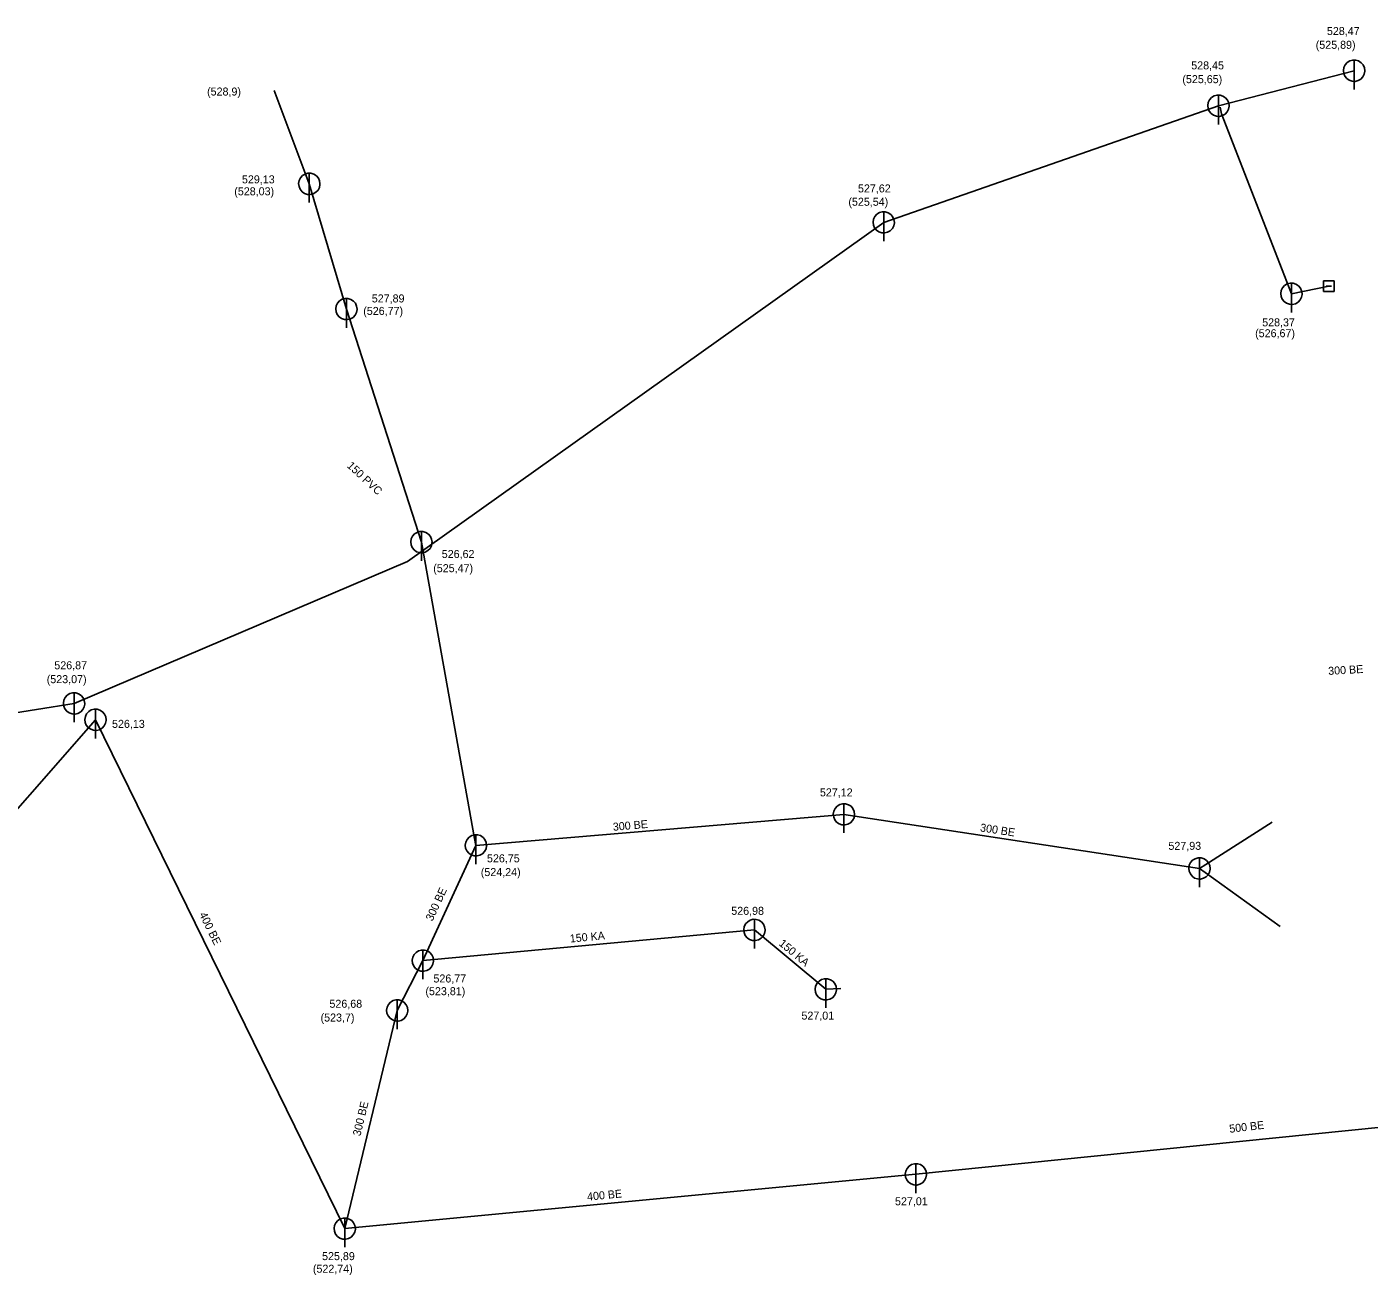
# Model space of a CAD drawing. Extents: x -476058 to -471893, y -1155786 to -1152000.
# Drawn here: x -473628.2 to -473502.4, y -1153925.1 to -1153808.2 of the extents above; entities that cross this region are included whole.
import ezdxf

# ---------------------------------------------------------------- set-up
doc = ezdxf.new("R2010")
doc.units = 0
for name, color, linetype in [('Vrstva 10', 7, 'Continuous'), ('Vrstva 18', 7, 'Continuous'), ('Vrstva 19', 7, 'Continuous'), ('Vrstva 3', 7, 'Continuous'), ('Vrstva 35', 7, 'Continuous'), ('Vrstva 4', 7, 'Continuous'), ('Vrstva 45', 7, 'Continuous'), ('Vrstva 46', 7, 'Continuous'), ('Vrstva 50', 7, 'Continuous'), ('Vrstva 51', 7, 'Continuous')]:
    doc.layers.add(name, color=color, linetype=linetype)

msp = doc.modelspace()

# ---------------------------------------------------------------- linework, layer by layer
at = {"layer": 'Vrstva 10'}
for p, q in [((-473503.76, -1153811.26), (-473503.76, -1153814.01)), ((-473516.48, -1153814.54), (-473516.48, -1153817.29)), ((-473601.71, -1153821.86), (-473601.71, -1153824.61)), ((-473547.86, -1153825.48), (-473547.86, -1153828.23)), ((-473509.64, -1153832.17), (-473509.64, -1153834.92)), ((-473505.64, -1153831.96), (-473506.64, -1153831.96)), ((-473506.64, -1153831.96), (-473506.64, -1153832.96)), ((-473505.64, -1153832.96), (-473505.64, -1153831.96)), ((-473598.23, -1153833.6), (-473598.23, -1153836.35)), ((-473506.64, -1153832.96), (-473505.64, -1153832.96)), ((-473505.89, -1153832.46), (-473506.39, -1153832.46)), ((-473591.2, -1153855.45), (-473591.2, -1153858.19)), ((-473623.76, -1153870.56), (-473623.76, -1153873.31)), ((-473621.75, -1153872.09), (-473621.75, -1153874.84)), ((-473551.59, -1153880.96), (-473551.59, -1153883.7)), ((-473586.08, -1153883.86), (-473586.08, -1153886.61)), ((-473518.26, -1153886.02), (-473518.26, -1153888.77)), ((-473559.98, -1153891.79), (-473559.98, -1153894.53)), ((-473591.06, -1153894.66), (-473591.06, -1153897.41)), ((-473553.29, -1153897.35), (-473553.29, -1153900.1)), ((-473593.46, -1153899.33), (-473593.46, -1153902.08)), ((-473544.84, -1153914.69), (-473544.84, -1153917.44)), ((-473598.39, -1153919.78), (-473598.39, -1153922.53))]:
    msp.add_line(p, q, dxfattribs=at)
for points in [[(-473502.76, -1153812.26), (-473502.8, -1153811.98), (-473502.92, -1153811.72), (-473503.1, -1153811.51), (-473503.34, -1153811.35), (-473503.6, -1153811.27), (-473503.89, -1153811.27), (-473504.16, -1153811.34), (-473504.4, -1153811.49), (-473504.59, -1153811.7), (-473504.71, -1153811.95), (-473504.76, -1153812.23), (-473504.73, -1153812.51), (-473504.62, -1153812.77), (-473504.44, -1153812.99), (-473504.21, -1153813.15), (-473503.94, -1153813.24), (-473503.66, -1153813.26), (-473503.39, -1153813.19), (-473503.14, -1153813.05), (-473502.95, -1153812.84), (-473502.82, -1153812.59), (-473502.76, -1153812.32), (-473502.76, -1153812.26)], [(-473515.48, -1153815.54), (-473515.52, -1153815.27), (-473515.64, -1153815.01), (-473515.82, -1153814.79), (-473516.06, -1153814.64), (-473516.33, -1153814.56), (-473516.61, -1153814.55), (-473516.88, -1153814.63), (-473517.12, -1153814.78), (-473517.31, -1153814.99), (-473517.43, -1153815.24), (-473517.48, -1153815.52), (-473517.45, -1153815.8), (-473517.34, -1153816.06), (-473517.16, -1153816.28), (-473516.93, -1153816.44), (-473516.67, -1153816.53), (-473516.38, -1153816.54), (-473516.11, -1153816.47), (-473515.86, -1153816.33), (-473515.67, -1153816.13), (-473515.54, -1153815.88), (-473515.48, -1153815.6), (-473515.48, -1153815.54)], [(-473600.71, -1153822.86), (-473600.74, -1153822.58), (-473600.86, -1153822.33), (-473601.04, -1153822.11), (-473601.28, -1153821.96), (-473601.55, -1153821.88), (-473601.83, -1153821.87), (-473602.1, -1153821.95), (-473602.35, -1153822.09), (-473602.54, -1153822.3), (-473602.66, -1153822.56), (-473602.71, -1153822.84), (-473602.67, -1153823.12), (-473602.57, -1153823.38), (-473602.39, -1153823.6), (-473602.16, -1153823.76), (-473601.89, -1153823.85), (-473601.61, -1153823.86), (-473601.33, -1153823.79), (-473601.09, -1153823.65), (-473600.89, -1153823.45), (-473600.76, -1153823.2), (-473600.71, -1153822.92), (-473600.71, -1153822.86)], [(-473546.86, -1153826.48), (-473546.9, -1153826.2), (-473547.02, -1153825.94), (-473547.2, -1153825.73), (-473547.44, -1153825.57), (-473547.71, -1153825.49), (-473547.99, -1153825.49), (-473548.26, -1153825.56), (-473548.5, -1153825.71), (-473548.69, -1153825.92), (-473548.81, -1153826.17), (-473548.86, -1153826.45), (-473548.83, -1153826.73), (-473548.72, -1153826.99), (-473548.54, -1153827.21), (-473548.31, -1153827.37), (-473548.04, -1153827.46), (-473547.76, -1153827.47), (-473547.49, -1153827.41), (-473547.24, -1153827.27), (-473547.05, -1153827.06), (-473546.92, -1153826.81), (-473546.86, -1153826.53), (-473546.86, -1153826.48)], [(-473508.64, -1153833.17), (-473508.68, -1153832.89), (-473508.8, -1153832.63), (-473508.98, -1153832.42), (-473509.22, -1153832.27), (-473509.48, -1153832.18), (-473509.77, -1153832.18), (-473510.04, -1153832.25), (-473510.28, -1153832.4), (-473510.47, -1153832.61), (-473510.59, -1153832.86), (-473510.64, -1153833.14), (-473510.61, -1153833.42), (-473510.5, -1153833.68), (-473510.32, -1153833.9), (-473510.09, -1153834.06), (-473509.82, -1153834.15), (-473509.54, -1153834.17), (-473509.27, -1153834.1), (-473509.02, -1153833.96), (-473508.83, -1153833.75), (-473508.7, -1153833.5), (-473508.64, -1153833.23), (-473508.64, -1153833.17)], [(-473597.23, -1153834.6), (-473597.27, -1153834.32), (-473597.39, -1153834.06), (-473597.57, -1153833.85), (-473597.81, -1153833.69), (-473598.08, -1153833.61), (-473598.36, -1153833.61), (-473598.63, -1153833.68), (-473598.87, -1153833.83), (-473599.06, -1153834.04), (-473599.18, -1153834.29), (-473599.23, -1153834.57), (-473599.2, -1153834.85), (-473599.09, -1153835.11), (-473598.91, -1153835.33), (-473598.68, -1153835.49), (-473598.41, -1153835.58), (-473598.13, -1153835.59), (-473597.86, -1153835.53), (-473597.61, -1153835.39), (-473597.42, -1153835.18), (-473597.29, -1153834.93), (-473597.23, -1153834.65), (-473597.23, -1153834.6)], [(-473590.2, -1153856.45), (-473590.24, -1153856.17), (-473590.36, -1153855.91), (-473590.54, -1153855.7), (-473590.78, -1153855.54), (-473591.05, -1153855.46), (-473591.33, -1153855.45), (-473591.6, -1153855.53), (-473591.84, -1153855.68), (-473592.03, -1153855.89), (-473592.16, -1153856.14), (-473592.2, -1153856.42), (-473592.17, -1153856.7), (-473592.06, -1153856.96), (-473591.89, -1153857.18), (-473591.65, -1153857.34), (-473591.39, -1153857.43), (-473591.1, -1153857.44), (-473590.83, -1153857.37), (-473590.59, -1153857.23), (-473590.39, -1153857.03), (-473590.26, -1153856.78), (-473590.21, -1153856.5), (-473590.2, -1153856.45)], [(-473622.76, -1153871.56), (-473622.8, -1153871.28), (-473622.92, -1153871.02), (-473623.1, -1153870.81), (-473623.34, -1153870.66), (-473623.6, -1153870.57), (-473623.89, -1153870.57), (-473624.16, -1153870.64), (-473624.4, -1153870.79), (-473624.59, -1153871), (-473624.71, -1153871.25), (-473624.76, -1153871.53), (-473624.73, -1153871.81), (-473624.62, -1153872.07), (-473624.44, -1153872.29), (-473624.21, -1153872.45), (-473623.94, -1153872.54), (-473623.66, -1153872.56), (-473623.39, -1153872.49), (-473623.14, -1153872.35), (-473622.95, -1153872.14), (-473622.82, -1153871.89), (-473622.76, -1153871.62), (-473622.76, -1153871.56)], [(-473620.75, -1153873.09), (-473620.79, -1153872.81), (-473620.91, -1153872.55), (-473621.09, -1153872.34), (-473621.33, -1153872.19), (-473621.6, -1153872.1), (-473621.88, -1153872.1), (-473622.15, -1153872.17), (-473622.39, -1153872.32), (-473622.58, -1153872.53), (-473622.7, -1153872.78), (-473622.75, -1153873.06), (-473622.72, -1153873.34), (-473622.61, -1153873.6), (-473622.43, -1153873.82), (-473622.2, -1153873.98), (-473621.93, -1153874.07), (-473621.65, -1153874.09), (-473621.38, -1153874.02), (-473621.13, -1153873.88), (-473620.94, -1153873.67), (-473620.81, -1153873.42), (-473620.75, -1153873.15), (-473620.75, -1153873.09)], [(-473550.59, -1153881.96), (-473550.62, -1153881.68), (-473550.74, -1153881.42), (-473550.92, -1153881.2), (-473551.16, -1153881.05), (-473551.43, -1153880.97), (-473551.71, -1153880.96), (-473551.98, -1153881.04), (-473552.22, -1153881.19), (-473552.41, -1153881.4), (-473552.54, -1153881.65), (-473552.59, -1153881.93), (-473552.55, -1153882.21), (-473552.44, -1153882.47), (-473552.27, -1153882.69), (-473552.04, -1153882.85), (-473551.77, -1153882.94), (-473551.48, -1153882.95), (-473551.21, -1153882.88), (-473550.97, -1153882.74), (-473550.77, -1153882.54), (-473550.64, -1153882.29), (-473550.59, -1153882.01), (-473550.59, -1153881.96)], [(-473585.08, -1153884.86), (-473585.12, -1153884.58), (-473585.24, -1153884.32), (-473585.42, -1153884.11), (-473585.66, -1153883.95), (-473585.93, -1153883.87), (-473586.21, -1153883.87), (-473586.48, -1153883.94), (-473586.72, -1153884.09), (-473586.91, -1153884.3), (-473587.03, -1153884.55), (-473587.08, -1153884.83), (-473587.05, -1153885.11), (-473586.94, -1153885.37), (-473586.76, -1153885.59), (-473586.53, -1153885.75), (-473586.26, -1153885.84), (-473585.98, -1153885.85), (-473585.71, -1153885.79), (-473585.46, -1153885.65), (-473585.27, -1153885.44), (-473585.14, -1153885.19), (-473585.08, -1153884.91), (-473585.08, -1153884.86)], [(-473517.26, -1153887.02), (-473517.29, -1153886.74), (-473517.41, -1153886.49), (-473517.6, -1153886.27), (-473517.83, -1153886.12), (-473518.1, -1153886.03), (-473518.38, -1153886.03), (-473518.66, -1153886.11), (-473518.9, -1153886.25), (-473519.09, -1153886.46), (-473519.21, -1153886.72), (-473519.26, -1153887), (-473519.22, -1153887.28), (-473519.11, -1153887.54), (-473518.94, -1153887.76), (-473518.71, -1153887.92), (-473518.44, -1153888.01), (-473518.16, -1153888.02), (-473517.88, -1153887.95), (-473517.64, -1153887.81), (-473517.44, -1153887.61), (-473517.31, -1153887.36), (-473517.26, -1153887.08), (-473517.26, -1153887.02)], [(-473558.98, -1153892.79), (-473559.02, -1153892.51), (-473559.13, -1153892.25), (-473559.32, -1153892.03), (-473559.55, -1153891.88), (-473559.82, -1153891.8), (-473560.1, -1153891.79), (-473560.38, -1153891.87), (-473560.61, -1153892.02), (-473560.8, -1153892.23), (-473560.93, -1153892.48), (-473560.98, -1153892.76), (-473560.94, -1153893.04), (-473560.84, -1153893.3), (-473560.66, -1153893.52), (-473560.43, -1153893.68), (-473560.16, -1153893.77), (-473559.88, -1153893.78), (-473559.6, -1153893.71), (-473559.36, -1153893.57), (-473559.16, -1153893.37), (-473559.03, -1153893.12), (-473558.98, -1153892.84), (-473558.98, -1153892.79)], [(-473590.06, -1153895.66), (-473590.1, -1153895.38), (-473590.22, -1153895.12), (-473590.4, -1153894.91), (-473590.64, -1153894.76), (-473590.91, -1153894.67), (-473591.19, -1153894.67), (-473591.46, -1153894.74), (-473591.7, -1153894.89), (-473591.89, -1153895.1), (-473592.01, -1153895.35), (-473592.06, -1153895.63), (-473592.03, -1153895.91), (-473591.92, -1153896.17), (-473591.74, -1153896.39), (-473591.51, -1153896.55), (-473591.24, -1153896.64), (-473590.96, -1153896.66), (-473590.69, -1153896.59), (-473590.44, -1153896.45), (-473590.25, -1153896.24), (-473590.12, -1153895.99), (-473590.06, -1153895.72), (-473590.06, -1153895.66)], [(-473552.29, -1153898.35), (-473552.33, -1153898.08), (-473552.44, -1153897.82), (-473552.62, -1153897.6), (-473552.86, -1153897.45), (-473553.13, -1153897.37), (-473553.41, -1153897.36), (-473553.68, -1153897.44), (-473553.92, -1153897.59), (-473554.11, -1153897.79), (-473554.24, -1153898.05), (-473554.29, -1153898.33), (-473554.25, -1153898.61), (-473554.15, -1153898.87), (-473553.97, -1153899.09), (-473553.74, -1153899.25), (-473553.47, -1153899.34), (-473553.19, -1153899.35), (-473552.91, -1153899.28), (-473552.67, -1153899.14), (-473552.47, -1153898.94), (-473552.34, -1153898.69), (-473552.29, -1153898.41), (-473552.29, -1153898.35)], [(-473592.46, -1153900.33), (-473592.5, -1153900.05), (-473592.62, -1153899.79), (-473592.8, -1153899.58), (-473593.04, -1153899.43), (-473593.3, -1153899.34), (-473593.59, -1153899.34), (-473593.86, -1153899.41), (-473594.1, -1153899.56), (-473594.29, -1153899.77), (-473594.41, -1153900.02), (-473594.46, -1153900.3), (-473594.43, -1153900.58), (-473594.32, -1153900.84), (-473594.14, -1153901.06), (-473593.91, -1153901.22), (-473593.64, -1153901.31), (-473593.36, -1153901.33), (-473593.09, -1153901.26), (-473592.84, -1153901.12), (-473592.65, -1153900.91), (-473592.52, -1153900.66), (-473592.46, -1153900.39), (-473592.46, -1153900.33)], [(-473543.84, -1153915.69), (-473543.88, -1153915.41), (-473544, -1153915.15), (-473544.18, -1153914.94), (-473544.42, -1153914.78), (-473544.68, -1153914.7), (-473544.97, -1153914.7), (-473545.24, -1153914.77), (-473545.48, -1153914.92), (-473545.67, -1153915.13), (-473545.79, -1153915.38), (-473545.84, -1153915.66), (-473545.81, -1153915.94), (-473545.7, -1153916.2), (-473545.52, -1153916.42), (-473545.29, -1153916.58), (-473545.02, -1153916.67), (-473544.74, -1153916.69), (-473544.47, -1153916.62), (-473544.22, -1153916.48), (-473544.03, -1153916.27), (-473543.9, -1153916.02), (-473543.84, -1153915.75), (-473543.84, -1153915.69)], [(-473597.39, -1153920.78), (-473597.43, -1153920.5), (-473597.55, -1153920.24), (-473597.73, -1153920.03), (-473597.97, -1153919.88), (-473598.23, -1153919.79), (-473598.52, -1153919.79), (-473598.79, -1153919.86), (-473599.03, -1153920.01), (-473599.22, -1153920.22), (-473599.34, -1153920.47), (-473599.39, -1153920.75), (-473599.36, -1153921.03), (-473599.25, -1153921.29), (-473599.07, -1153921.51), (-473598.84, -1153921.67), (-473598.57, -1153921.76), (-473598.29, -1153921.78), (-473598.02, -1153921.71), (-473597.77, -1153921.57), (-473597.58, -1153921.36), (-473597.45, -1153921.11), (-473597.39, -1153920.84), (-473597.39, -1153920.78)]]:
    msp.add_lwpolyline(points, dxfattribs=at)
at = {"layer": 'Vrstva 35'}
for p, q in [((-473547.86, -1153826.48), (-473592.5, -1153858.26)), ((-473592.5, -1153858.26), (-473623.76, -1153871.56))]:
    msp.add_line(p, q, dxfattribs=at)
for points in [[(-473503.76, -1153812.26), (-473516.48, -1153815.54)], [(-473516.48, -1153815.54), (-473547.86, -1153826.48)], [(-473623.76, -1153871.56), (-473652.03, -1153876.05)]]:
    msp.add_lwpolyline(points, dxfattribs=at)
at = {"layer": 'Vrstva 45'}
for points in [[(-473621.75, -1153873.09), (-473646.84, -1153901.7)], [(-473598.39, -1153920.78), (-473621.75, -1153873.09)], [(-473551.59, -1153881.96), (-473586.08, -1153884.86)], [(-473518.26, -1153887.02), (-473551.59, -1153881.96)], [(-473586.08, -1153884.86), (-473591.06, -1153895.66)], [(-473591.06, -1153895.66), (-473593.46, -1153900.33)], [(-473593.46, -1153900.33), (-473598.39, -1153920.78)], [(-473544.84, -1153915.69), (-473598.39, -1153920.78)]]:
    msp.add_lwpolyline(points, dxfattribs=at)
at = {"layer": 'Vrstva 46'}
msp.add_lwpolyline([(-473487.58, -1153909.91), (-473544.84, -1153915.69)], dxfattribs=at)
at = {"layer": 'Vrstva 50'}
for points in [[(-473605.01, -1153814.11), (-473601.71, -1153822.86), (-473598.23, -1153834.6)], [(-473506.14, -1153832.46), (-473509.64, -1153833.17), (-473516.18, -1153816.32), (-473516.32, -1153815.69)], [(-473598.23, -1153834.6), (-473591.2, -1153856.45)], [(-473591.2, -1153856.45), (-473586.23, -1153884.23)], [(-473586.23, -1153884.23), (-473586.08, -1153884.86)], [(-473559.98, -1153892.79), (-473589.99, -1153895.56)], [(-473551.87, -1153898.29), (-473553.29, -1153898.35), (-473559.98, -1153892.79)], [(-473589.99, -1153895.56), (-473591.06, -1153895.66)]]:
    msp.add_lwpolyline(points, dxfattribs=at)
at = {"layer": 'Vrstva 51'}
for points in [[(-473511.44, -1153882.68), (-473517.67, -1153886.65), (-473518.26, -1153887.02)], [(-473510.68, -1153892.47), (-473517.73, -1153887.4), (-473518.26, -1153887.02)]]:
    msp.add_lwpolyline(points, dxfattribs=at)

# ---------------------------------------------------------------- texts
at = {"layer": 'Vrstva 18'}
for s, rotation, p in [('300 BE', 4.8102, (-473573.22, -1153883.5)), ('300 BE', 351.3539, (-473538.86, -1153883.54)), ('300 BE', 65.2578, (-473590.16, -1153892.02)), ('400 BE', 296.097, (-473612.05, -1153891.33)), ('300 BE', 76.446, (-473596.92, -1153912.15)), ('500 BE', 6.6985, (-473515.42, -1153911.8)), ('400 BE', 5.4297, (-473575.63, -1153918.16))]:
    msp.add_text(s, height=0.75, rotation=rotation, dxfattribs=at).set_placement(p)
at = {"layer": 'Vrstva 19'}
for s, rotation, p in [('150 PVC', 317.0907, (-473598.23, -1153849.36)), ('300 BE', 3.313, (-473506.17, -1153868.89)), ('150 KA', 5.2822, (-473577.25, -1153893.97)), ('150 KA', 320.2248, (-473557.75, -1153894.16))]:
    msp.add_text(s, height=0.75, rotation=rotation, dxfattribs=at).set_placement(p)
at = {"layer": 'Vrstva 3'}
for s, p in [('528,47', (-473506.31, -1153808.92)), ('528,45', (-473519.03, -1153812.14)), ('529,13', (-473608.02, -1153822.82)), ('527,62', (-473550.27, -1153823.67)), ('527,89', (-473595.85, -1153833.98)), ('528,37', (-473512.38, -1153836.22)), ('526,62', (-473589.29, -1153857.93)), ('526,87', (-473625.61, -1153868.36)), ('526,13', (-473620.2, -1153873.85)), ('527,12', (-473553.84, -1153880.27)), ('527,93', (-473521.17, -1153885.28)), ('526,75', (-473585.05, -1153886.45)), ('526,98', (-473562.15, -1153891.37)), ('526,77', (-473590.07, -1153897.71)), ('526,68', (-473599.82, -1153900.08)), ('527,01', (-473555.57, -1153901.19)), ('527,01', (-473546.8, -1153918.59)), ('525,89', (-473600.51, -1153923.73))]:
    msp.add_text(s, height=0.75, dxfattribs=at).set_placement(p)
at = {"layer": 'Vrstva 4'}
for s, p in [('(525,89)', (-473507.36, -1153810.21)), ('(525,65)', (-473519.86, -1153813.43)), ('(528,9)', (-473611.29, -1153814.59)), ('(528,03)', (-473608.74, -1153823.94)), ('(525,54)', (-473551.17, -1153824.92)), ('(526,77)', (-473596.65, -1153835.15)), ('(526,67)', (-473513.04, -1153837.24)), ('(525,47)', (-473590.09, -1153859.26)), ('(523,07)', (-473626.32, -1153869.66)), ('(524,24)', (-473585.63, -1153887.74)), ('(523,81)', (-473590.82, -1153898.9)), ('(523,7)', (-473600.65, -1153901.37)), ('(522,74)', (-473601.37, -1153924.91))]:
    msp.add_text(s, height=0.75, dxfattribs=at).set_placement(p)

doc.saveas('drawing.dxf')
